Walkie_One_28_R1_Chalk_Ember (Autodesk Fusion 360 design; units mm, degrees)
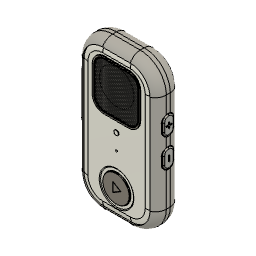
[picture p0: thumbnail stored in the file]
description: Open CASCADE Model
part number: Walkie_One_Concept_27_R2_REFERENCE_ASSEMBLY
description: Part Number
part number: C27_R2_04_Status_Lens
part number: C27_R2_05_Front_Switch_Clamp
part number: C27_R2_08_Volume_Down_Rigid_Carrier
part number: C27_R2_10_Front_Action_Pewter_Cap
part number: C27_R2_11_Front_Action_Bond_Film
part number: C27_R2_12_Volume_Up_Pewter_Cap
part number: C27_R2_13_Volume_Up_Bond_Film
part number: C27_R2_14_Volume_Down_Pewter_Cap
part number: C27_R2_15_Volume_Down_Bond_Film
base_feature "Base Feature1" bodies "C28_R1_01_Front_Shell_Chalk_Mesh_Round_Controls"
base_feature "Base Feature1"
base_feature "Base Feature1" bodies "C28_R1_03_Round_Action_Carrier_Original_Retention"
base_feature "Base Feature1" bodies "C28_R1_04_Circular_Status_Lens_Original_Collector"
base_feature "Base Feature1"
base_feature "Base Feature1"
base_feature "Base Feature1"
base_feature "Base Feature1"
base_feature "Base Feature1"
base_feature "Base Feature1" bodies "C28_R1_10_Round_Brushed_Steel_Play_Cap"
base_feature "Base Feature1" bodies "C28_R1_11_Round_Play_Bond_Film"
base_feature "Base Feature1"
base_feature "Base Feature1"
base_feature "Base Feature1"
base_feature "Base Feature1"
base_feature "Base Feature1" bodies "C28_R1_16_Smooth_Ember_PTT_Grip"
base_feature "Base Feature1"
base_feature "Base Feature1"
base_feature "Base Feature1"
base_feature "Base Feature1"
base_feature "Base Feature1"
base_feature "Base Feature1"
base_feature "Base Feature1"
base_feature "Base Feature1"
base_feature "Base Feature1"
base_feature "Base Feature1"
base_feature "Base Feature1"
base_feature "Base Feature1"
base_feature "Base Feature1"
base_feature "Base Feature1"
base_feature "Base Feature1"
base_feature "Base Feature1"
base_feature "Base Feature1"
base_feature "Base Feature1"
base_feature "Base Feature1"
base_feature "Base Feature1"
base_feature "Base Feature1"
base_feature "Base Feature1"
base_feature "Base Feature1"
base_feature "Base Feature1"
base_feature "Base Feature1"
base_feature "Base Feature1"
base_feature "Base Feature1"
base_feature "Base Feature1"
base_feature "Base Feature1"
base_feature "Base Feature1"
base_feature "Base Feature1"
base_feature "Base Feature1"
base_feature "Base Feature1"
base_feature "Base Feature1"
base_feature "Base Feature1"
base_feature "Base Feature1"
base_feature "Base Feature1"
base_feature "Base Feature1"
base_feature "Base Feature1"
base_feature "Base Feature1"
base_feature "Base Feature1"
base_feature "Base Feature1"
base_feature "Base Feature1"
base_feature "Base Feature1"
base_feature "Base Feature1"
base_feature "Base Feature1"
base_feature "Base Feature1"
base_feature "Base Feature1"
base_feature "Base Feature1"
base_feature "Base Feature1"
base_feature "Base Feature1"
base_feature "Base Feature1"
base_feature "Base Feature1"
base_feature "Base Feature1"
base_feature "Base Feature1"
base_feature "Base Feature1"
base_feature "Base Feature1"
base_feature "Base Feature1"
base_feature "Base Feature1"
base_feature "Base Feature1"
base_feature "Base Feature1"
base_feature "Base Feature1"
base_feature "Base Feature1"
base_feature "Base Feature1"
base_feature "Base Feature1"
base_feature "Base Feature1"
base_feature "Base Feature1"
base_feature "Base Feature1"
base_feature "Base Feature1"
base_feature "Base Feature1"
base_feature "Base Feature1"
base_feature "Base Feature1"
base_feature "Base Feature1"
base_feature "Base Feature1"
base_feature "Base Feature1"
base_feature "Base Feature1"
base_feature "Base Feature1"
base_feature "Base Feature1"
base_feature "Base Feature1"
base_feature "Base Feature1"
base_feature "Base Feature1"
base_feature "Base Feature1"
base_feature "Base Feature1"
base_feature "Base Feature1"
base_feature "Base Feature1"
base_feature "Base Feature1"
base_feature "Base Feature1"
base_feature "Base Feature1"
base_feature "Base Feature1"
base_feature "Base Feature1"
base_feature "Base Feature1"
base_feature "Base Feature1"
base_feature "Base Feature1"
base_feature "Base Feature1"
base_feature "Base Feature1"
base_feature "Base Feature1"
base_feature "Base Feature1"
base_feature "Base Feature1"
base_feature "Base Feature1"
base_feature "Base Feature1"
base_feature "Base Feature1"
base_feature "Base Feature1"
base_feature "Base Feature1"
base_feature "Base Feature1"
base_feature "Base Feature1"
base_feature "Base Feature1"
base_feature "Base Feature1"
base_feature "Base Feature1"
base_feature "Base Feature1"
base_feature "Base Feature1"
base_feature "Base Feature1"
base_feature "Base Feature1"
base_feature "Base Feature1"
base_feature "Base Feature1"
base_feature "Base Feature1"
base_feature "Base Feature1"
base_feature "Base Feature1"
base_feature "Base Feature1"
base_feature "Base Feature1"
base_feature "Base Feature1"
base_feature "Base Feature1"
base_feature "Base Feature1"
base_feature "Base Feature1"
base_feature "Base Feature1"
base_feature "Base Feature1"
base_feature "Base Feature1"
base_feature "Base Feature1"
base_feature "Base Feature1"
base_feature "Base Feature1"
base_feature "Base Feature1"
base_feature "Base Feature1"
base_feature "Base Feature1"
base_feature "Base Feature1"
base_feature "Base Feature1"
base_feature "Base Feature1"
base_feature "Base Feature1"
base_feature "Base Feature1"
base_feature "Base Feature1"
base_feature "Base Feature1"
base_feature "Base Feature1"
base_feature "Base Feature1"
base_feature "Base Feature1"
base_feature "Base Feature1"
base_feature "Base Feature1"
base_feature "Base Feature1"
base_feature "Base Feature1"
base_feature "Base Feature1"
base_feature "Base Feature1"
base_feature "Base Feature1"
base_feature "Base Feature1"
base_feature "Base Feature1"
base_feature "Base Feature1"
base_feature "Base Feature1"
base_feature "Base Feature1"
base_feature "Base Feature1"
base_feature "Base Feature1"
base_feature "Base Feature1"
base_feature "Base Feature1"
base_feature "Base Feature1"
base_feature "Base Feature1"
base_feature "Base Feature1"
base_feature "Base Feature1"
base_feature "Base Feature1"
base_feature "Base Feature1"
base_feature "Base Feature1"
base_feature "Base Feature1"
base_feature "Base Feature1"
base_feature "Base Feature1"
base_feature "Base Feature1"
base_feature "Base Feature1"
base_feature "Base Feature1"
base_feature "Base Feature1"
base_feature "Base Feature1"
base_feature "Base Feature1"
base_feature "Base Feature1"
base_feature "Base Feature1"
base_feature "Base Feature1"
base_feature "Base Feature1"
base_feature "Base Feature1"
base_feature "Base Feature1"
base_feature "Base Feature1"
base_feature "Base Feature1"
base_feature "Base Feature1"
base_feature "Base Feature1"
base_feature "Base Feature1"
base_feature "Base Feature1"
base_feature "Base Feature1"
base_feature "Base Feature1"
base_feature "Base Feature1"
base_feature "Base Feature1"
base_feature "Base Feature1"
base_feature "Base Feature1"
base_feature "Base Feature1"
base_feature "Base Feature1"
base_feature "Base Feature1"
base_feature "Base Feature1"
base_feature "Base Feature1"
base_feature "Base Feature1"
base_feature "Base Feature1"
base_feature "Base Feature1"
base_feature "Base Feature1"
base_feature "Base Feature1"
base_feature "Base Feature1"
base_feature "Base Feature1"
base_feature "Base Feature1"
base_feature "Base Feature1"
base_feature "Base Feature1"
base_feature "Base Feature1"
base_feature "Base Feature1"
base_feature "Base Feature1"
base_feature "Base Feature1"
base_feature "Base Feature1"
base_feature "Base Feature1"
base_feature "Base Feature1"
base_feature "Base Feature1"
base_feature "Base Feature1"
base_feature "Base Feature1"
base_feature "Base Feature1"
base_feature "Base Feature1"
base_feature "Base Feature1"
base_feature "Base Feature1"
base_feature "Base Feature1"
base_feature "Base Feature1"
base_feature "Base Feature1"
base_feature "Base Feature1"
base_feature "Base Feature1"
base_feature "Base Feature1"
base_feature "Base Feature1"
base_feature "Base Feature1"
base_feature "Base Feature1"
base_feature "Base Feature1"
base_feature "Base Feature1"
base_feature "Base Feature1"
base_feature "Base Feature1"
base_feature "Base Feature1"
base_feature "Base Feature1"
base_feature "Base Feature1"
base_feature "Base Feature1"
base_feature "Base Feature1"
base_feature "Base Feature1"
base_feature "Base Feature1"
base_feature "Base Feature1"
base_feature "Base Feature1"
base_feature "Base Feature1"
base_feature "Base Feature1"
base_feature "Base Feature1"
base_feature "Base Feature1"
base_feature "Base Feature1"
base_feature "Base Feature1"
base_feature "Base Feature1"
base_feature "Base Feature1"
base_feature "Base Feature1"
base_feature "Base Feature1"
base_feature "Base Feature1"
base_feature "Base Feature1"
base_feature "Base Feature1"
base_feature "Base Feature1"
base_feature "Base Feature1"
base_feature "Base Feature1"
base_feature "Base Feature1"
base_feature "Base Feature1"
base_feature "Base Feature1"
base_feature "Base Feature1"
base_feature "Base Feature1"
base_feature "Base Feature1"
base_feature "Base Feature1"
base_feature "Base Feature1"
base_feature "Base Feature1"
base_feature "Base Feature1"
base_feature "Base Feature1"
base_feature "Base Feature1"
base_feature "Base Feature1"
base_feature "Base Feature1"
base_feature "Base Feature1"
base_feature "Base Feature1"
base_feature "Base Feature1"
base_feature "Base Feature1"
base_feature "Base Feature1"
base_feature "Base Feature1"
base_feature "Base Feature1"
base_feature "Base Feature1"
base_feature "Base Feature1"
base_feature "Base Feature1"
base_feature "Base Feature1"
base_feature "Base Feature1"
base_feature "Base Feature1"
base_feature "Base Feature1"
base_feature "Base Feature1"
base_feature "Base Feature1"
base_feature "Base Feature1"
base_feature "Base Feature1"
base_feature "Base Feature1"
base_feature "Base Feature1"
base_feature "Base Feature1"
base_feature "Base Feature1"
base_feature "Base Feature1"
base_feature "Base Feature1"
base_feature "Base Feature1"
base_feature "Base Feature1"
base_feature "Base Feature1"
base_feature "Base Feature1"
base_feature "Base Feature1"
base_feature "Base Feature1"
base_feature "Base Feature1"
base_feature "Base Feature1"
base_feature "Base Feature1"
base_feature "Base Feature1"
base_feature "Base Feature1"
base_feature "Base Feature1"
base_feature "Base Feature1"
base_feature "Base Feature1"
base_feature "Base Feature1"
base_feature "Base Feature1"
base_feature "Base Feature1"
base_feature "Base Feature1"
base_feature "Base Feature1"
base_feature "Base Feature1"
base_feature "Base Feature1"
base_feature "Base Feature1"
base_feature "Base Feature1"
base_feature "Base Feature1"
base_feature "Base Feature1" bodies "C28_R1_57_Stainless_Grille_Bezel"
base_feature "Base Feature1" bodies "C28_R1_58_Grille_Perimeter_Bond_Film"
base_feature "Base Feature1" bodies "C28_R1_59_Mesh_Edge_Bond_Film"
base_feature "Base Feature1" bodies "C28_R1_60_Black_Acoustic_Scrim"
base_feature "Base Feature1" bodies "C28_R1_61_Graphite_Woven_Mesh_REFERENCE_RODS_001", "C28_R1_61_Graphite_Woven_Mesh_REFERENCE_RODS_002", "C28_R1_61_Graphite_Woven_Mesh_REFERENCE_RODS_003", "C28_R1_61_Graphite_Woven_Mesh_REFERENCE_RODS_004", "C28_R1_61_Graphite_Woven_Mesh_REFERENCE_RODS_005", "C28_R1_61_Graphite_Woven_Mesh_REFERENCE_RODS_006", "C28_R1_61_Graphite_Woven_Mesh_REFERENCE_RODS_007", "C28_R1_61_Graphite_Woven_Mesh_REFERENCE_RODS_008"
base_feature "Base Feature1" bodies "C28_R1_62_Scrim_Perimeter_Bond_Film"
sketch "C28_R1_CUT_Mesh_45x47_R10" plane through (0, 0, 0) normal (0, 0, 1) x axis (1, 0, 0)
  line L1 (12.5, -23.5) -> (-12.5, -23.5)
  line L2 (22.5, 13.5) -> (22.5, -13.5)
  line L3 (-12.5, 23.5) -> (12.5, 23.5)
  line L4 (-22.5, -13.5) -> (-22.5, 13.5)
  arc A1 centre (12.5, -13.5) radius 10 clockwise from (22.5, -13.5) to (12.5, -23.5)
  arc A2 centre (12.5, 13.5) radius 10 clockwise from (12.5, 23.5) to (22.5, 13.5)
  arc A3 centre (-12.5, 13.5) radius 10 clockwise from (-22.5, 13.5) to (-12.5, 23.5)
  arc A4 centre (-12.5, -13.5) radius 10 clockwise from (-12.5, -23.5) to (-22.5, -13.5)
sketch "C28_R1_CUT_Scrim_44_8x46_8_R9_9" plane through (0, 0, 0) normal (0, 0, 1) x axis (1, 0, 0)
  line L1 (12.5, -23.4) -> (-12.5, -23.4)
  line L2 (22.4, 13.5) -> (22.4, -13.5)
  line L3 (-12.5, 23.4) -> (12.5, 23.4)
  line L4 (-22.4, -13.5) -> (-22.4, 13.5)
  arc A1 centre (12.5, -13.5) radius 9.9 clockwise from (22.4, -13.5) to (12.5, -23.4)
  arc A2 centre (12.5, 13.5) radius 9.9 clockwise from (12.5, 23.4) to (22.4, 13.5)
  arc A3 centre (-12.5, 13.5) radius 9.9 clockwise from (-22.4, 13.5) to (-12.5, 23.4)
  arc A4 centre (-12.5, -13.5) radius 9.9 clockwise from (-12.5, -23.4) to (-22.4, -13.5)
sketch "C28_R1_CUT_Bezel_Plan_48x50" plane through (0, 0, 0) normal (0, 0, 1) x axis (1, 0, 0)
  line L1 (12.5, -25) -> (-12.5, -25)
  line L2 (24, 13.5) -> (24, -13.5)
  line L3 (-12.5, 25) -> (12.5, 25)
  line L4 (-24, -13.5) -> (-24, 13.5)
  line L5 (12.5, -23) -> (-12.5, -23)
  line L6 (22, 13.5) -> (22, -13.5)
  line L7 (-12.5, 23) -> (12.5, 23)
  line L8 (-22, -13.5) -> (-22, 13.5)
  arc A1 centre (12.5, -13.5) radius 11.5 clockwise from (24, -13.5) to (12.5, -25)
  arc A2 centre (12.5, 13.5) radius 11.5 clockwise from (12.5, 25) to (24, 13.5)
  arc A3 centre (-12.5, 13.5) radius 11.5 clockwise from (-24, 13.5) to (-12.5, 25)
  arc A4 centre (-12.5, -13.5) radius 11.5 clockwise from (-12.5, -25) to (-24, -13.5)
  arc A5 centre (12.5, -13.5) radius 9.5 clockwise from (22, -13.5) to (12.5, -23)
  arc A6 centre (12.5, 13.5) radius 9.5 clockwise from (12.5, 23) to (22, 13.5)
  arc A7 centre (-12.5, 13.5) radius 9.5 clockwise from (-22, 13.5) to (-12.5, 23)
  arc A8 centre (-12.5, -13.5) radius 9.5 clockwise from (-12.5, -23) to (-22, -13.5)
sketch "C28_R1_CUT_Grille_Perimeter_Bond" plane through (0, 0, 0) normal (0, 0, 1) x axis (1, 0, 0)
  line L1 (12.5, -24.9) -> (-12.5, -24.9)
  line L2 (23.9, 13.5) -> (23.9, -13.5)
  line L3 (-12.5, 24.9) -> (12.5, 24.9)
  line L4 (-23.9, -13.5) -> (-23.9, 13.5)
  line L5 (12.5, -23.8) -> (-12.5, -23.8)
  line L6 (22.8, 13.5) -> (22.8, -13.5)
  line L7 (-12.5, 23.8) -> (12.5, 23.8)
  line L8 (-22.8, -13.5) -> (-22.8, 13.5)
  arc A1 centre (12.5, -13.5) radius 11.4 clockwise from (23.9, -13.5) to (12.5, -24.9)
  arc A2 centre (12.5, 13.5) radius 11.4 clockwise from (12.5, 24.9) to (23.9, 13.5)
  arc A3 centre (-12.5, 13.5) radius 11.4 clockwise from (-23.9, 13.5) to (-12.5, 24.9)
  arc A4 centre (-12.5, -13.5) radius 11.4 clockwise from (-12.5, -24.9) to (-23.9, -13.5)
  arc A5 centre (12.5, -13.5) radius 10.3 clockwise from (22.8, -13.5) to (12.5, -23.8)
  arc A6 centre (12.5, 13.5) radius 10.3 clockwise from (12.5, 23.8) to (22.8, 13.5)
  arc A7 centre (-12.5, 13.5) radius 10.3 clockwise from (-22.8, 13.5) to (-12.5, 23.8)
  arc A8 centre (-12.5, -13.5) radius 10.3 clockwise from (-12.5, -23.8) to (-22.8, -13.5)
sketch "C28_R1_CUT_Mesh_Edge_Bond" plane through (0, 0, 0) normal (0, 0, 1) x axis (1, 0, 0)
  line L1 (12.5, -23.5) -> (-12.5, -23.5)
  line L2 (22.5, 13.5) -> (22.5, -13.5)
  line L3 (-12.5, 23.5) -> (12.5, 23.5)
  line L4 (-22.5, -13.5) -> (-22.5, 13.5)
  line L5 (12.5, -23) -> (-12.5, -23)
  line L6 (22, 13.5) -> (22, -13.5)
  line L7 (-12.5, 23) -> (12.5, 23)
  line L8 (-22, -13.5) -> (-22, 13.5)
  arc A1 centre (12.5, -13.5) radius 10 clockwise from (22.5, -13.5) to (12.5, -23.5)
  arc A2 centre (12.5, 13.5) radius 10 clockwise from (12.5, 23.5) to (22.5, 13.5)
  arc A3 centre (-12.5, 13.5) radius 10 clockwise from (-22.5, 13.5) to (-12.5, 23.5)
  arc A4 centre (-12.5, -13.5) radius 10 clockwise from (-12.5, -23.5) to (-22.5, -13.5)
  arc A5 centre (12.5, -13.5) radius 9.5 clockwise from (22, -13.5) to (12.5, -23)
  arc A6 centre (12.5, 13.5) radius 9.5 clockwise from (12.5, 23) to (22, 13.5)
  arc A7 centre (-12.5, 13.5) radius 9.5 clockwise from (-22, 13.5) to (-12.5, 23)
  arc A8 centre (-12.5, -13.5) radius 9.5 clockwise from (-12.5, -23) to (-22, -13.5)
sketch "C28_R1_CUT_Scrim_Perimeter_Bond" plane through (0, 0, 0) normal (0, 0, 1) x axis (1, 0, 0)
  line L1 (12.5, -23.3) -> (-12.5, -23.3)
  line L2 (22.3, 13.5) -> (22.3, -13.5)
  line L3 (-12.5, 23.3) -> (12.5, 23.3)
  line L4 (-22.3, -13.5) -> (-22.3, 13.5)
  line L5 (12.5, -22.4) -> (-12.5, -22.4)
  line L6 (21.4, 13.5) -> (21.4, -13.5)
  line L7 (-12.5, 22.4) -> (12.5, 22.4)
  line L8 (-21.4, -13.5) -> (-21.4, 13.5)
  arc A1 centre (12.5, -13.5) radius 9.8 clockwise from (22.3, -13.5) to (12.5, -23.3)
  arc A2 centre (12.5, 13.5) radius 9.8 clockwise from (12.5, 23.3) to (22.3, 13.5)
  arc A3 centre (-12.5, 13.5) radius 9.8 clockwise from (-22.3, 13.5) to (-12.5, 23.3)
  arc A4 centre (-12.5, -13.5) radius 9.8 clockwise from (-12.5, -23.3) to (-22.3, -13.5)
  arc A5 centre (12.5, -13.5) radius 8.9 clockwise from (21.4, -13.5) to (12.5, -22.4)
  arc A6 centre (12.5, 13.5) radius 8.9 clockwise from (12.5, 22.4) to (21.4, 13.5)
  arc A7 centre (-12.5, 13.5) radius 8.9 clockwise from (-21.4, 13.5) to (-12.5, 22.4)
  arc A8 centre (-12.5, -13.5) radius 8.9 clockwise from (-12.5, -22.4) to (-21.4, -13.5)
fillet "Fillet1" radius 0.6
work_plane "WorkPlane1" AlongDistance 0.51 ExtraOffset 0
sketch "Play symbol laser outline" plane through (0, 0, 0.51) normal (0, 0, 1) x axis (1, 0, 0)
  line L1 (5, -47) -> (-3.3, -52)
  line L2 (-3.3, -42) -> (5, -47)
  line L3 (-3.3, -52) -> (-3.3, -42)
  line L4 (4.42, -47) -> (-3, -51.469)
  line L5 (-3, -42.531) -> (4.42, -47)
  line L6 (-3, -51.469) -> (-3, -42.531)
extrude "Extrude1" cut sketch "Play symbol laser outline" along normal blind 0.1
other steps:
create_component "CreateComponent1"
create_component "CreateComponent2"
create_component "CreateComponent3"
create_component "CreateComponent4"
create_component "CreateComponent5"
create_component "CreateComponent6"
create_component "CreateComponent7"
create_component "CreateComponent8"
create_component "CreateComponent9"
create_component "CreateComponent10"
create_component "CreateComponent11"
create_component "CreateComponent12"
create_component "CreateComponent13"
create_component "CreateComponent14"
create_component "CreateComponent15"
create_component "CreateComponent16"
create_component "CreateComponent17"
create_component "CreateComponent18"
create_component "CreateComponent19"
create_component "CreateComponent20"
create_component "CreateComponent21"
create_component "CreateComponent22"
create_component "CreateComponent23"
create_component "CreateComponent24"
create_component "CreateComponent25"
create_component "CreateComponent26"
create_component "CreateComponent27"
create_component "CreateComponent28"
create_component "CreateComponent29"
create_component "CreateComponent30"
create_component "CreateComponent31"
create_component "CreateComponent32"
create_component "CreateComponent33"
create_component "CreateComponent34"
create_component "CreateComponent35"
create_component "CreateComponent36"
create_component "CreateComponent37"
create_component "CreateComponent38"
create_component "CreateComponent39"
create_component "CreateComponent40"
create_component "CreateComponent41"
create_component "CreateComponent42"
create_component "CreateComponent43"
create_component "CreateComponent44"
create_component "CreateComponent45"
create_component "CreateComponent46"
create_component "CreateComponent47"
create_component "CreateComponent48"
create_component "CreateComponent49"
create_component "CreateComponent50"
create_component "CreateComponent51"
create_component "CreateComponent52"
create_component "CreateComponent53"
create_component "CreateComponent54"
create_component "CreateComponent55"
create_component "CreateComponent56"
create_component "CreateComponent57"
create_component "CreateComponent58"
create_component "CreateComponent59"
create_component "CreateComponent60"
create_component "CreateComponent61"
create_component "CreateComponent62"
create_component "CreateComponent63"
create_component "CreateComponent64"
create_component "CreateComponent65"
create_component "CreateComponent66"
create_component "CreateComponent67"
create_component "CreateComponent68"
create_component "CreateComponent69"
create_component "CreateComponent70"
create_component "CreateComponent71"
create_component "CreateComponent72"
create_component "CreateComponent73"
create_component "CreateComponent74"
create_component "CreateComponent75"
create_component "CreateComponent76"
create_component "CreateComponent77"
create_component "CreateComponent78"
create_component "CreateComponent79"
create_component "CreateComponent80"
create_component "CreateComponent81"
create_component "CreateComponent82"
create_component "CreateComponent83"
create_component "CreateComponent84"
create_component "CreateComponent85"
create_component "CreateComponent86"
create_component "CreateComponent1"
create_component "CreateComponent2"
create_component "CreateComponent3"
create_component "CreateComponent4"
create_component "CreateComponent5"
create_component "CreateComponent6"
create_component "CreateComponent7"
create_component "CreateComponent8"
create_component "CreateComponent9"
create_component "CreateComponent10"
create_component "CreateComponent11"
create_component "CreateComponent12"
create_component "CreateComponent13"
create_component "CreateComponent14"
create_component "CreateComponent15"
create_component "CreateComponent16"
create_component "CreateComponent17"
create_component "CreateComponent18"
create_component "CreateComponent19"
create_component "CreateComponent20"
create_component "CreateComponent21"
create_component "CreateComponent22"
create_component "CreateComponent23"
create_component "CreateComponent24"
create_component "CreateComponent25"
create_component "CreateComponent26"
create_component "CreateComponent27"
create_component "CreateComponent28"
create_component "CreateComponent29"
create_component "CreateComponent30"
create_component "CreateComponent31"
create_component "CreateComponent32"
create_component "CreateComponent33"
create_component "CreateComponent34"
create_component "CreateComponent35"
create_component "CreateComponent36"
create_component "CreateComponent37"
create_component "CreateComponent38"
create_component "CreateComponent39"
create_component "CreateComponent40"
create_component "CreateComponent41"
create_component "CreateComponent42"
create_component "CreateComponent43"
create_component "CreateComponent44"
create_component "CreateComponent45"
create_component "CreateComponent46"
create_component "CreateComponent47"
create_component "CreateComponent48"
create_component "CreateComponent49"
create_component "CreateComponent50"
create_component "CreateComponent51"
create_component "CreateComponent52"
create_component "CreateComponent53"
create_component "CreateComponent54"
create_component "CreateComponent55"
create_component "CreateComponent56"
create_component "CreateComponent57"
create_component "CreateComponent58"
create_component "CreateComponent59"
create_component "CreateComponent60"
create_component "CreateComponent61"
create_component "CreateComponent62"
create_component "CreateComponent63"
create_component "CreateComponent64"
create_component "CreateComponent65"
create_component "CreateComponent66"
create_component "CreateComponent67"
create_component "CreateComponent68"
create_component "CreateComponent69"
create_component "CreateComponent70"
create_component "CreateComponent71"
create_component "CreateComponent72"
create_component "CreateComponent73"
create_component "CreateComponent74"
create_component "CreateComponent75"
create_component "CreateComponent76"
create_component "CreateComponent77"
create_component "CreateComponent78"
create_component "CreateComponent79"
create_component "CreateComponent80"
create_component "CreateComponent81"
create_component "CreateComponent82"
create_component "CreateComponent83"
create_component "CreateComponent84"
create_component "CreateComponent85"
create_component "CreateComponent86"
create_component "CreateComponent87"
create_component "CreateComponent88"
create_component "CreateComponent89"
create_component "CreateComponent90"
create_component "CreateComponent91"
create_component "CreateComponent92"
create_component "CreateComponent93"
create_component "CreateComponent94"
create_component "CreateComponent95"
create_component "CreateComponent96"
create_component "CreateComponent97"
create_component "CreateComponent98"
create_component "CreateComponent99"
create_component "CreateComponent100"
create_component "CreateComponent101"
create_component "CreateComponent102"
create_component "CreateComponent103"
create_component "CreateComponent104"
create_component "CreateComponent105"
create_component "CreateComponent106"
create_component "CreateComponent107"
create_component "CreateComponent108"
create_component "CreateComponent109"
create_component "CreateComponent110"
create_component "CreateComponent111"
create_component "CreateComponent112"
create_component "CreateComponent113"
create_component "CreateComponent114"
create_component "CreateComponent115"
create_component "CreateComponent116"
create_component "CreateComponent117"
create_component "CreateComponent118"
create_component "CreateComponent119"
create_component "CreateComponent120"
create_component "CreateComponent121"
create_component "CreateComponent122"
create_component "CreateComponent123"
create_component "CreateComponent124"
create_component "CreateComponent125"
create_component "CreateComponent126"
create_component "CreateComponent127"
create_component "CreateComponent128"
create_component "CreateComponent129"
create_component "CreateComponent130"
create_component "CreateComponent131"
create_component "CreateComponent132"
create_component "CreateComponent133"
create_component "CreateComponent134"
create_component "CreateComponent135"
create_component "CreateComponent136"
create_component "CreateComponent137"
create_component "CreateComponent138"
create_component "CreateComponent139"
create_component "CreateComponent140"
create_component "CreateComponent141"
create_component "CreateComponent142"
create_component "CreateComponent143"
create_component "CreateComponent144"
create_component "CreateComponent145"
create_component "CreateComponent146"
create_component "CreateComponent147"
create_component "CreateComponent148"
create_component "CreateComponent149"
create_component "CreateComponent150"
create_component "CreateComponent151"
create_component "CreateComponent152"
create_component "CreateComponent153"
create_component "CreateComponent154"
create_component "CreateComponent155"
create_component "CreateComponent156"
create_component "CreateComponent157"
create_component "CreateComponent158"
create_component "CreateComponent159"
create_component "CreateComponent160"
create_component "CreateComponent161"
create_component "CreateComponent162"
create_component "CreateComponent163"
create_component "CreateComponent164"
create_component "CreateComponent165"
create_component "CreateComponent166"
create_component "CreateComponent167"
create_component "CreateComponent168"
create_component "CreateComponent169"
create_component "CreateComponent170"
create_component "CreateComponent171"
create_component "CreateComponent172"
create_component "CreateComponent173"
create_component "CreateComponent174"
create_component "CreateComponent175"
create_component "CreateComponent176"
create_component "CreateComponent177"
create_component "CreateComponent178"
create_component "CreateComponent179"
create_component "CreateComponent180"
create_component "CreateComponent181"
create_component "CreateComponent182"
create_component "CreateComponent183"
create_component "CreateComponent184"
create_component "CreateComponent185"
create_component "CreateComponent186"
create_component "CreateComponent187"
create_component "CreateComponent188"
create_component "CreateComponent189"
create_component "CreateComponent190"
create_component "CreateComponent191"
create_component "CreateComponent192"
create_component "CreateComponent193"
create_component "CreateComponent194"
create_component "CreateComponent195"
create_component "CreateComponent196"
create_component "CreateComponent197"
create_component "CreateComponent198"
create_component "CreateComponent199"
create_component "CreateComponent200"
create_component "CreateComponent87"
create_component "CreateComponent1"
create_component "CreateComponent2"
create_component "CreateComponent88"
create_component "CreateComponent1"
create_component "CreateComponent2"
create_component "CreateComponent3"
create_component "CreateComponent4"
create_component "CreateComponent89"
create_component "CreateComponent1"
create_component "CreateComponent2"
create_component "CreateComponent90"
create_component "CreateComponent1"
create_component "CreateComponent2"
create_component "CreateComponent3"
create_component "CreateComponent4"
create_component "CreateComponent5"
create_component "CreateComponent6"
create_component "CreateComponent91"
create_component "CreateComponent1"
create_component "CreateComponent2"
create_component "CreateComponent3"
create_component "CreateComponent4"
create_component "CreateComponent5"
create_component "CreateComponent6"
create_component "CreateComponent7"
create_component "CreateComponent8"
create_component "CreateComponent92"
create_component "CreateComponent1"
create_component "CreateComponent2"
create_component "CreateComponent3"
create_component "CreateComponent4"
create_component "CreateComponent5"
create_component "CreateComponent6"
create_component "CreateComponent7"
create_component "CreateComponent93"
create_component "CreateComponent1"
create_component "CreateComponent2"
create_component "CreateComponent3"
create_component "CreateComponent4"
create_component "CreateComponent5"
create_component "CreateComponent6"
create_component "CreateComponent7"
create_component "CreateComponent94"
create_component "CreateComponent1"
create_component "CreateComponent2"
create_component "CreateComponent3"
create_component "CreateComponent4"
create_component "CreateComponent5"
create_component "CreateComponent6"
create_component "CreateComponent7"
create_component "CreateComponent95"
create_component "CreateComponent1"
create_component "CreateComponent2"
create_component "CreateComponent3"
create_component "CreateComponent4"
create_component "CreateComponent5"
create_component "CreateComponent6"
create_component "CreateComponent7"
create_component "CreateComponent96"
create_component "CreateComponent97"
create_component "CreateComponent98"
create_component "CreateComponent99"
create_component "CreateComponent100"
create_component "CreateComponent101"
create_component "CreateComponent102"
create_component "CreateComponent103"
named bodies: "C28_R1_04_Circular_Status_Lens_Original_Collector", "C28_R1_10_Round_Brushed_Steel_Play_Cap", "C28_R1_11_Round_Play_Bond_Film", "C28_R1_03_Round_Action_Carrier_Original_Retention", "C28_R1_16_Smooth_Ember_PTT_Grip", "C28_R1_01_Front_Shell_Chalk_Mesh_Round_Controls", "C28_R1_57_Stainless_Grille_Bezel", "C28_R1_58_Grille_Perimeter_Bond_Film", "C28_R1_59_Mesh_Edge_Bond_Film", "C28_R1_60_Black_Acoustic_Scrim", "C28_R1_61_Graphite_Woven_Mesh_REFERENCE_RODS_001", "C28_R1_61_Graphite_Woven_Mesh_REFERENCE_RODS_002", "C28_R1_61_Graphite_Woven_Mesh_REFERENCE_RODS_003", "C28_R1_61_Graphite_Woven_Mesh_REFERENCE_RODS_004", "C28_R1_61_Graphite_Woven_Mesh_REFERENCE_RODS_005", "C28_R1_61_Graphite_Woven_Mesh_REFERENCE_RODS_006", "C28_R1_61_Graphite_Woven_Mesh_REFERENCE_RODS_007", "C28_R1_61_Graphite_Woven_Mesh_REFERENCE_RODS_008", "C28_R1_61_Graphite_Woven_Mesh_REFERENCE_RODS_009", "C28_R1_61_Graphite_Woven_Mesh_REFERENCE_RODS_010", "C28_R1_61_Graphite_Woven_Mesh_REFERENCE_RODS_011", "C28_R1_61_Graphite_Woven_Mesh_REFERENCE_RODS_012", "C28_R1_61_Graphite_Woven_Mesh_REFERENCE_RODS_013", "C28_R1_61_Graphite_Woven_Mesh_REFERENCE_RODS_014", "C28_R1_61_Graphite_Woven_Mesh_REFERENCE_RODS_015", "C28_R1_61_Graphite_Woven_Mesh_REFERENCE_RODS_016", "C28_R1_61_Graphite_Woven_Mesh_REFERENCE_RODS_017", "C28_R1_61_Graphite_Woven_Mesh_REFERENCE_RODS_018", "C28_R1_61_Graphite_Woven_Mesh_REFERENCE_RODS_019", "C28_R1_61_Graphite_Woven_Mesh_REFERENCE_RODS_020", "C28_R1_61_Graphite_Woven_Mesh_REFERENCE_RODS_021", "C28_R1_61_Graphite_Woven_Mesh_REFERENCE_RODS_022", "C28_R1_61_Graphite_Woven_Mesh_REFERENCE_RODS_023", "C28_R1_61_Graphite_Woven_Mesh_REFERENCE_RODS_024", "C28_R1_61_Graphite_Woven_Mesh_REFERENCE_RODS_025", "C28_R1_61_Graphite_Woven_Mesh_REFERENCE_RODS_026", "C28_R1_61_Graphite_Woven_Mesh_REFERENCE_RODS_027", "C28_R1_61_Graphite_Woven_Mesh_REFERENCE_RODS_028", "C28_R1_61_Graphite_Woven_Mesh_REFERENCE_RODS_029", "C28_R1_61_Graphite_Woven_Mesh_REFERENCE_RODS_030", "C28_R1_61_Graphite_Woven_Mesh_REFERENCE_RODS_031", "C28_R1_61_Graphite_Woven_Mesh_REFERENCE_RODS_032", "C28_R1_61_Graphite_Woven_Mesh_REFERENCE_RODS_033", "C28_R1_61_Graphite_Woven_Mesh_REFERENCE_RODS_034", "C28_R1_61_Graphite_Woven_Mesh_REFERENCE_RODS_035", "C28_R1_61_Graphite_Woven_Mesh_REFERENCE_RODS_036", "C28_R1_61_Graphite_Woven_Mesh_REFERENCE_RODS_037", "C28_R1_61_Graphite_Woven_Mesh_REFERENCE_RODS_038", "C28_R1_61_Graphite_Woven_Mesh_REFERENCE_RODS_039", "C28_R1_61_Graphite_Woven_Mesh_REFERENCE_RODS_040", "C28_R1_61_Graphite_Woven_Mesh_REFERENCE_RODS_041", "C28_R1_61_Graphite_Woven_Mesh_REFERENCE_RODS_042", "C28_R1_61_Graphite_Woven_Mesh_REFERENCE_RODS_043", "C28_R1_61_Graphite_Woven_Mesh_REFERENCE_RODS_044", "C28_R1_61_Graphite_Woven_Mesh_REFERENCE_RODS_045", "C28_R1_61_Graphite_Woven_Mesh_REFERENCE_RODS_046", "C28_R1_61_Graphite_Woven_Mesh_REFERENCE_RODS_047", "C28_R1_61_Graphite_Woven_Mesh_REFERENCE_RODS_048", "C28_R1_61_Graphite_Woven_Mesh_REFERENCE_RODS_049", "C28_R1_61_Graphite_Woven_Mesh_REFERENCE_RODS_050"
